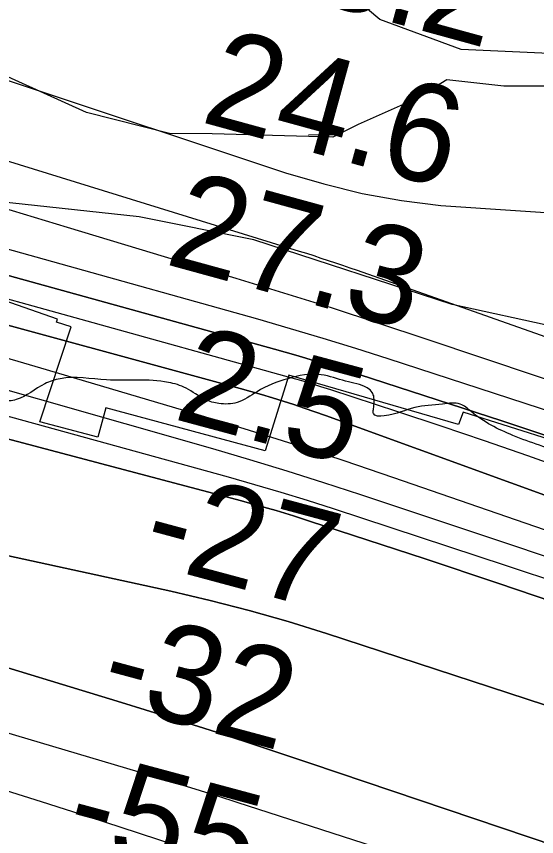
# Model space of a CAD drawing. Extents: x 3329297 to 3367176, y 649250 to 674653.
# Drawn here: x 3335095 to 3335450, y 671176 to 671736 of the extents above; entities that cross this region are included whole.
import ezdxf

# ---------------------------------------------------------------- set-up
doc = ezdxf.new("R2010")
doc.units = 0
for name, color, linetype in [('V-BORW-LINE', 7, 'Continuous'), ('V-RIVR-EDGE', 7, 'Continuous'), ('V-RIVR-RANG', 7, 'Continuous'), ('V-RRAP-RVMT', 7, 'Continuous'), ('V-SITE-VEGE', 7, 'Continuous'), ('V-TOPO-DPTH', 7, 'Continuous'), ('V-TOPO-MAJR', 7, 'Continuous'), ('V-TOPO-MINR', 7, 'Continuous'), ('V-TOPO-WATR', 7, 'Continuous'), ('V-WETL-SWMP', 7, 'Continuous')]:
    doc.layers.add(name, color=color, linetype=linetype)

msp = doc.modelspace()

# ---------------------------------------------------------------- linework, layer by layer
at = {"layer": 'V-BORW-LINE'}
msp.add_lwpolyline([(3335544.13, 671706.51), (3335398.54, 671713), (3335343.11, 671733.58), (3335283.83, 671783.37)], dxfattribs=at)
at = {"layer": 'V-RIVR-EDGE'}
msp.add_spline([(3339166.35, 669632.45), (3339148.52, 669636.37), (3339138.83, 669636.78), (3339122.94, 669641.48), (3339105.12, 669646.95), (3339096.99, 669652.01), (3339093.12, 669656.29), (3339089.26, 669664.44), (3339086.56, 669669.1), (3339078.82, 669674.94), (3339053.64, 669688.18), (3339028.47, 669702.21), (3339020.72, 669706.49), (3339018, 669704.17), (3339012.57, 669704.57), (3339008.7, 669708.07), (3339008.32, 669710.4), (3339007.94, 669713.12), (3339007.56, 669715.06), (3338988.58, 669723.63), (3338974.64, 669732.59), (3338973.09, 669734.53), (3338972.71, 669738.02), (3338974.27, 669740.35), (3338974.28, 669743.84), (3338966.94, 669753.94), (3338965.01, 669758.6), (3338963.85, 669760.54), (3338956.49, 669764.43), (3338944.87, 669769.5), (3338928.21, 669778.08), (3338920.86, 669785.07), (3338906.56, 669803.34), (3338897.28, 669814.22), (3338888, 669824.71), (3338880.26, 669833.26), (3338874.07, 669838.71), (3338867.87, 669840.27), (3338862.06, 669843), (3338858.57, 669843.01), (3338858.58, 669844.95), (3338858.24, 669867.83), (3338860.58, 669870.93), (3338861.75, 669873.25), (3338861.76, 669876.35), (3338860.21, 669879.46), (3338854.02, 669882.58), (3338849.02, 669903.14), (3338843.63, 669917.51), (3338832.81, 669931.11), (3338822.75, 669940.83), (3338804.56, 669955.22), (3338800.68, 669956.78), (3338796.03, 669956.79), (3338788.66, 669955.26), (3338782.44, 669952.17), (3338775.47, 669955.68), (3338770.44, 669960.35), (3338765.41, 669965.01), (3338754.18, 669972.41), (3338742.57, 669981.36), (3338728.24, 669988.76), (3338714.68, 669995), (3338701.13, 670003.56), (3338693.4, 670012.11), (3338687.99, 670020.27), (3338682.59, 670033.47), (3338677.18, 670040.46), (3338665.17, 670046.31), (3338655.1, 670048.66), (3338655.48, 670045.95), (3338653.54, 670045.56), (3338643.46, 670046.36), (3338635.32, 670050.26), (3338633, 670052.98), (3338626.41, 670055.33), (3338615.17, 670057.29), (3338608.97, 670058.08), (3338601.61, 670062.76), (3338592.32, 670069.37), (3338582.25, 670071.72), (3338574.11, 670074.46), (3338568.3, 670078.74), (3338562.5, 670084.57), (3338561.34, 670087.67), (3338554.75, 670088.85), (3338551.26, 670089.25), (3338548.94, 670091.97), (3338544.31, 670098.58), (3338517.19, 670108.73), (3338513.32, 670111.84), (3338511.39, 670115.72), (3338497.82, 670118.86), (3338480, 670125.88), (3338471.48, 670130.17), (3338466.45, 670134.83), (3338451.73, 670140.3), (3338441.26, 670142.65), (3338438.16, 670142.27), (3338431.18, 670145.39), (3338420.34, 670150.07), (3338407.93, 670152.43), (3338393.21, 670156.73), (3338378.49, 670165.69), (3338345.2, 670189.43), (3338316.55, 670206.56), (3338280.93, 670231.47), (3338237.55, 670254.45), (3338210.45, 670270.81), (3338182.57, 670289.88), (3338148.9, 670317.5), (3338126.07, 670336.94), (3338116.01, 670348.22), (3338106.73, 670356.77), (3338093.56, 670363.78), (3338076.9, 670368.87), (3338057.53, 670376.28), (3338042.81, 670383.3), (3338026.54, 670392.65), (3338007.18, 670402.39), (3337994, 670405.52), (3337971.52, 670413.34), (3337948.66, 670420.76), (3337916.51, 670434.03), (3337912.65, 670440.63), (3337911.11, 670448.78), (3337908.8, 670453.82), (3337904.54, 670455.77), (3337890.98, 670459.68), (3337883.62, 670464.74), (3337879.36, 670466.69), (3337872.38, 670467.1), (3337862.68, 670467.12), (3337849.88, 670465.99), (3337839.8, 670463.69), (3337826.22, 670462.56), (3337810.72, 670465.7), (3337802.19, 670469.21), (3337788.25, 670478.16), (3337779.73, 670480.51), (3337774.3, 670481.69), (3337768.89, 670486.74), (3337764.63, 670490.63), (3337755.72, 670494.92), (3337749.13, 670496.88), (3337745.26, 670497.27), (3337740.6, 670495.35), (3337738.66, 670496.13), (3337735.18, 670499.24), (3337729.76, 670503.52), (3337724.73, 670508.18), (3337720.08, 670512.07), (3337706.13, 670514.43), (3337677.86, 670531.18), (3337643.77, 670545.22), (3337600.78, 670567.05), (3337560.1, 670585.37), (3337510.14, 670611.87), (3337463.28, 670636.42), (3337442.36, 670644.22), (3337416.78, 670652.43), (3337405.55, 670657.5), (3337401.68, 670661.39), (3337400.13, 670663.33), (3337395.49, 670665.67), (3337388.89, 670666.07), (3337376.88, 670670.76), (3337362.94, 670677.77), (3337340.87, 670690.62), (3337309.5, 670706.99), (3337291.29, 670714.79), (3337276.18, 670722.97), (3337252.56, 670736.99), (3337220.04, 670756.85), (3337154.99, 670798.5), (3337124.41, 670821.07), (3337111.24, 670827.31), (3337094.19, 670832.78), (3337075.97, 670836.7), (3337050.39, 670842.59), (3337028.69, 670849.62), (3337007.78, 670860.53), (3336991.89, 670867.94), (3336983.37, 670871.06), (3336969.03, 670873.42), (3336939.95, 670875.43), (3336901.97, 670884.45), (3336863.6, 670895.79), (3336821.37, 670910.63), (3336786.5, 670926.23), (3336740.02, 670949.61), (3336682.31, 670976.12), (3336635.44, 670997.18), (3336603.68, 671013.55), (3336585.47, 671022.51), (3336583.15, 671026.4), (3336580.06, 671031.06), (3336576.19, 671034.56), (3336549.46, 671045.09), (3336500.24, 671058.01), (3336451.41, 671070.16), (3336425.44, 671074.49), (3336399.85, 671076.49), (3336361.07, 671078.91), (3336337.43, 671082.85), (3336313.4, 671088.34), (3336290.92, 671094.6), (3336280.46, 671097.34), (3336275.41, 671097.35), (3336257.58, 671097.39), (3336194.82, 671123.92), (3336129.35, 671154.33), (3336078.61, 671179.66), (3336032.91, 671203.04), (3335979.46, 671230.32), (3335943.05, 671245.54), (3335907.79, 671259.2), (3335894.23, 671264.66), (3335887.64, 671265.45), (3335873.31, 671273.63), (3335871.38, 671277.13), (3335862.86, 671281.41), (3335831.09, 671293.51), (3335799.33, 671308.72), (3335763.7, 671327.42), (3335724.58, 671346.9), (3335714.51, 671351.97), (3335703.27, 671355.1), (3335699.01, 671358.21), (3335680.04, 671369.9), (3335645.95, 671385.49), (3335603.71, 671399.17), (3335573.09, 671406.61), (3335518.06, 671419.93), (3335470.4, 671436.73), (3335433.98, 671449.62), (3335405.32, 671465.97), (3335397.96, 671471.03), (3335385.94, 671471.06), (3335366.94, 671468.78), (3335345.98, 671463.02), (3335338.62, 671464.59), (3335338.62, 671467.3), (3335339.03, 671475.83), (3335337.87, 671478.94), (3335334.39, 671482.05), (3335319.67, 671486.74), (3335303, 671491.05), (3335280.12, 671488.39), (3335259.15, 671479.52), (3335245.56, 671472.19), (3335233.15, 671471.44), (3335223.85, 671474.18), (3335210.68, 671481.97), (3335198.67, 671485.88), (3335156.4, 671487.53), (3335124.61, 671488.39), (3335114.13, 671484.92), (3335094.71, 671474.11), (3335085.4, 671473.36), (3335075.32, 671475.71), (3335065.63, 671477.67), (3335064.86, 671478.45), (3335067.59, 671483.1), (3335066.81, 671484.65), (3335063.72, 671489.31), (3335039.71, 671501.39), (3335020.73, 671509.2), (3335003.28, 671511.95), (3334994.76, 671515.46), (3334990.89, 671517.03), (3334963, 671533.38), (3334933.18, 671549.36), (3334916.12, 671551.34), (3334894.42, 671557.6), (3334863.43, 671571.25), (3334847.95, 671581.75), (3334834.78, 671587.99), (3334809.21, 671598.53), (3334767.76, 671617.24), (3334744.9, 671627.77), (3334711.2, 671642.2), (3334691.44, 671649.23), (3334670.12, 671653.16), (3334647.65, 671659.81), (3334620.14, 671672.29), (3334605.42, 671678.53), (3334581, 671683.24), (3334555.81, 671689.12), (3334542.23, 671688.38), (3334534.09, 671688.79), (3334531.39, 671696.55), (3334523.66, 671706.27), (3334505.85, 671714.84), (3334480.26, 671719.17), (3334460.49, 671721.93), (3334457, 671720.39), (3334455.05, 671716.91), (3334456.59, 671713.8), (3334463.19, 671714.56), (3334467.45, 671712.22), (3334467.44, 671710.28), (3334462.78, 671708.35), (3334446.88, 671706.84), (3334429.04, 671707.66), (3334403.46, 671713.93), (3334397.66, 671718.6), (3334391.46, 671722.88), (3334378.67, 671723.69), (3334340.28, 671727.27), (3334305.39, 671730.07), (3334290.26, 671730.11), (3334281.35, 671731.68), (3334271.66, 671734.81), (3334266.23, 671735.6), (3334258.08, 671732.9), (3334246.43, 671726.73), (3334241.39, 671726.35), (3334232.48, 671729.48), (3334218.91, 671729.9), (3334190.6, 671730.74), (3334178.97, 671731.94), (3334163.47, 671737.4), (3334156.1, 671736.65), (3334151.44, 671732.39), (3334148.33, 671732.4), (3334142.53, 671735.91), (3334132.83, 671736.32), (3334110.73, 671737.53), (3334106.86, 671739.48), (3334099.89, 671744.15), (3334081.28, 671748.08), (3334072.75, 671747.71), (3334041.74, 671753.61), (3334018.09, 671757.54), (3334010.35, 671760.28), (3333999.89, 671767.67), (3333992.15, 671771.95), (3333987.1, 671771.19), (3333984.38, 671768.48), (3333980.12, 671768.49), (3333976.64, 671772.77), (3333969.66, 671775.11), (3333958.81, 671778.24), (3333949.91, 671783.31), (3333945.64, 671782.93), (3333941.37, 671782.16), (3333931.3, 671788.01), (3333925.87, 671788.02), (3333915.4, 671788.82), (3333900.29, 671791.57), (3333878.2, 671798.61), (3333856.9, 671811.07), (3333845.68, 671822.73), (3333832.9, 671828.97), (3333818.18, 671834.82), (3333817.41, 671837.15), (3333813.53, 671837.55), (3333800.36, 671841.85), (3333795.71, 671844.96), (3333793.79, 671851.56), (3333792.24, 671854.28), (3333782.95, 671858.18), (3333767.85, 671869.46), (3333755.47, 671879.57), (3333746.17, 671884.64), (3333742.68, 671886.2), (3333733.76, 671885.83), (3333720.97, 671886.64), (3333714.38, 671889.76), (3333707.8, 671895.2), (3333701.62, 671902.59), (3333696.98, 671908.42), (3333690.4, 671913.09), (3333677.23, 671920.49), (3333664.47, 671934.87), (3333650.92, 671945.76), (3333635.04, 671952), (3333625.75, 671959.78), (3333617.63, 671968.72), (3333606.39, 671969.91), (3333600.97, 671974.19), (3333597.87, 671978.08), (3333590.14, 671988.96), (3333572.36, 672009.16), (3333553.4, 672029.38), (3333532.11, 672045.72), (3333511.21, 672062.06), (3333486.44, 672080.35), (3333466.3, 672090.87), (3333451.59, 672102.92), (3333445.79, 672109.53), (3333446.58, 672114.96), (3333429.16, 672126.25), (3333421.43, 672137.9), (3333420.68, 672148.76), (3333415.26, 672151.1), (3333404.71, 672151.61)], degree=3, dxfattribs=at)
at = {"layer": 'V-RRAP-RVMT'}
for p, q in [((3335122.99, 671529.04), (3335008.31, 671568.73)), ((3335122.31, 671526.98), (3335122.99, 671529.04)), ((3335132.32, 671523.73), (3335122.31, 671526.98)), ((3335110.81, 671458.96), (3335132.32, 671523.73)), ((3335280.94, 671490.89), (3335264.68, 671439.19)), ((3335396.88, 671457.13), (3335280.94, 671490.89)), ((3335156.01, 671468.56), (3335150.35, 671448.52)), ((3335264.68, 671439.19), (3335156.01, 671468.56)), ((3335399.92, 671465.52), (3335396.88, 671457.13)), ((3335520.69, 671427.27), (3335399.92, 671465.52)), ((3335150.35, 671448.52), (3335110.81, 671458.96))]:
    msp.add_line(p, q, dxfattribs=at)
at = {"layer": 'V-SITE-VEGE'}
for p, q in [((3335178.56, 671598.82), (3335057.01, 671612.1)), ((3335256.94, 671583.2), (3335178.56, 671598.82)), ((3335392.38, 671539), (3335256.94, 671583.2)), ((3335468.16, 671522.52), (3335392.38, 671539))]:
    msp.add_line(p, q, dxfattribs=at)
at = {"layer": 'V-TOPO-DPTH'}
for points in [[(3334414.81, 671708.42), (3335247.62, 671481.74), (3335254.98, 671479.69), (3335262.32, 671477.57), (3335269.64, 671475.37), (3335276.94, 671473.11), (3335284.21, 671470.77), (3335291.46, 671468.35), (3335298.68, 671465.85), (3335305.88, 671463.29), (3335880.48, 671254.56), (3335895, 671249.28), (3335909.52, 671243.98), (3335924.03, 671238.66), (3335938.54, 671233.32), (3335958.74, 671225.88), (3335963.14, 671224.26), (3335967.55, 671222.63), (3335971.95, 671221.01), (3335976.36, 671219.39), (3336088.25, 671178.28), (3336148.58, 671156.07), (3336208.9, 671133.8)], [(3336208.9, 671133.8), (3336148.58, 671156.07), (3336088.25, 671178.28), (3335976.36, 671219.39), (3335971.95, 671221.01), (3335967.55, 671222.63), (3335963.14, 671224.26), (3335958.74, 671225.88), (3335938.54, 671233.32), (3335924.03, 671238.66), (3335909.52, 671243.98), (3335895, 671249.28), (3335880.48, 671254.56), (3335305.88, 671463.29), (3335298.68, 671465.85), (3335291.46, 671468.35), (3335284.21, 671470.77), (3335276.94, 671473.11), (3335269.64, 671475.37), (3335262.32, 671477.57), (3335254.98, 671479.69), (3335247.62, 671481.74), (3334414.81, 671708.42)], [(3334571.7, 671701.28), (3334636.35, 671683.68), (3334700.98, 671665.97), (3334765.58, 671648.18), (3335271.14, 671508.5), (3335285.64, 671504.39), (3335300.1, 671500.15), (3335314.5, 671495.72), (3335328.86, 671491.16), (3335426.31, 671459.51), (3335489.28, 671438.79), (3335552.15, 671417.76), (3335614.86, 671396.25), (3335677.46, 671374.43), (3335919.24, 671289.15), (3335948.69, 671278.79), (3335978.15, 671268.47), (3336007.64, 671258.22), (3336037.13, 671247.99), (3336091.93, 671229.07), (3336148.79, 671209.27), (3336205.57, 671189.27)], [(3336568.33, 670959.43), (3336013.25, 671169.68), (3335986.6, 671179.73), (3335959.92, 671189.73), (3335933.22, 671199.65), (3335906.49, 671209.52), (3335826.24, 671239.01), (3335759.26, 671263.28), (3335692.15, 671287.15), (3335624.82, 671310.41), (3335557.36, 671333.28), (3335329.99, 671409.19), (3335304.86, 671417.39), (3335279.66, 671425.37), (3335254.36, 671433.01), (3335228.99, 671440.42), (3334753.05, 671576.09), (3334687.65, 671594.63), (3334622.21, 671613.06), (3334556.73, 671631.3)], [(3336568.33, 670959.43), (3336013.25, 671169.68), (3335986.6, 671179.73), (3335959.92, 671189.73), (3335933.22, 671199.65), (3335906.49, 671209.52), (3335826.24, 671239.01), (3335759.26, 671263.28), (3335692.15, 671287.15), (3335624.82, 671310.41), (3335557.36, 671333.28), (3335329.99, 671409.19), (3335304.86, 671417.39), (3335279.66, 671425.37), (3335254.36, 671433.01), (3335228.99, 671440.42), (3334753.05, 671576.09), (3334687.65, 671594.63), (3334622.21, 671613.06), (3334556.73, 671631.3)], [(3334388.23, 671617.01), (3334612.96, 671565.53), (3334723.34, 671539.65), (3334833.53, 671513.02), (3334943.44, 671485.27), (3335053.17, 671456.77), (3335248.59, 671404.94), (3335260.44, 671401.69), (3335272.25, 671398.31), (3335284, 671394.72), (3335295.71, 671391), (3335373.28, 671365.6), (3335423.66, 671348.82), (3335473.92, 671331.71), (3335524, 671314.09), (3335573.97, 671296.13), (3335929.91, 671166.13), (3335941.22, 671161.95), (3335952.51, 671157.69), (3335963.76, 671153.34), (3335974.98, 671148.92), (3336067.07, 671112.17), (3336124.17, 671088.97), (3336181.05, 671065.27)], [(3336181.05, 671065.27), (3336124.17, 671088.97), (3336067.07, 671112.17), (3335974.98, 671148.92), (3335963.76, 671153.34), (3335952.51, 671157.69), (3335941.22, 671161.95), (3335929.91, 671166.13), (3335573.97, 671296.13), (3335524, 671314.09), (3335473.92, 671331.71), (3335423.66, 671348.82), (3335373.28, 671365.6), (3335295.71, 671391), (3335284, 671394.72), (3335272.25, 671398.31), (3335260.44, 671401.69), (3335248.59, 671404.94), (3335053.17, 671456.77), (3334943.44, 671485.27), (3334833.53, 671513.02), (3334723.34, 671539.65), (3334612.96, 671565.53), (3334388.23, 671617.01)], [(3334519.27, 671499.19), (3334616.45, 671474.69), (3334713.81, 671450.95), (3334811.45, 671428.35), (3334909.26, 671406.52), (3335200.32, 671343.34), (3335227.16, 671337.08), (3335253.85, 671330.27), (3335280.33, 671322.65), (3335306.65, 671314.49), (3335592.62, 671220.97), (3335650.83, 671201.08), (3335708.65, 671180.18), (3335765.91, 671157.75), (3335822.78, 671134.31), (3335889.72, 671105.67), (3335912.79, 671095.69), (3335935.79, 671085.57), (3335958.71, 671075.25), (3335981.57, 671064.8), (3336024.87, 671044.77), (3336069.52, 671024.66), (3336114.42, 671005.14), (3336159.71, 670986.52)], [(3334519.27, 671499.19), (3334616.45, 671474.69), (3334713.81, 671450.95), (3334811.45, 671428.35), (3334909.26, 671406.52), (3335200.32, 671343.34), (3335227.16, 671337.08), (3335253.85, 671330.27), (3335280.33, 671322.65), (3335306.65, 671314.49), (3335592.62, 671220.97), (3335650.83, 671201.08), (3335708.65, 671180.18), (3335765.91, 671157.75), (3335822.78, 671134.31), (3335889.72, 671105.67), (3335912.79, 671095.69), (3335935.79, 671085.57), (3335958.71, 671075.25), (3335981.57, 671064.8), (3336024.87, 671044.77), (3336069.52, 671024.66), (3336114.42, 671005.14), (3336159.71, 670986.52)], [(3336780.8, 670656.12), (3335991.84, 670987.78), (3335955.59, 671001.14), (3335919.26, 671014.3), (3335882.83, 671027.15), (3335846.32, 671039.81), (3335835.6, 671043.48), (3335793.67, 671057.79), (3335751.73, 671072.06), (3335709.77, 671086.28), (3335667.79, 671100.46), (3335295.98, 671225.76), (3335263.71, 671236.48), (3335231.39, 671247), (3335198.97, 671257.24), (3335166.49, 671267.3), (3335055.88, 671301), (3334967.96, 671327.48), (3334879.94, 671353.56), (3334791.74, 671379.07), (3334703.43, 671404.18), (3334375.38, 671496.31)], [(3334375.38, 671496.31), (3334703.43, 671404.18), (3334791.74, 671379.07), (3334879.94, 671353.56), (3334967.96, 671327.48), (3335055.88, 671301), (3335166.49, 671267.3), (3335198.97, 671257.24), (3335231.39, 671247), (3335263.71, 671236.48), (3335295.98, 671225.76), (3335667.79, 671100.46), (3335709.77, 671086.28), (3335751.73, 671072.06), (3335793.67, 671057.79), (3335835.6, 671043.48), (3335846.32, 671039.81), (3335882.83, 671027.15), (3335919.26, 671014.3), (3335955.59, 671001.14), (3335991.84, 670987.78), (3336780.8, 670656.12)]]:
    msp.add_lwpolyline(points, dxfattribs=at)
at = {"layer": 'V-TOPO-MAJR'}
for points in [[(3334465.48, 671896.3), (3334643.39, 671838.51), (3334755.96, 671801.81), (3334868.47, 671764.96), (3334980.91, 671727.87), (3335093.3, 671690.62), (3335278.64, 671628.98), (3335304.71, 671621.28), (3335331.03, 671614.78), (3335357.74, 671610.08), (3335384.69, 671606.58), (3336027.26, 671563.57), (3336045.4, 671559.52), (3336063.42, 671555), (3336909.83, 671212.05)], [(3336745.9, 671099.99), (3335993.18, 671327.49), (3335992.53, 671327.69), (3335990.58, 671328.31), (3335986.29, 671329.71), (3335983.51, 671330.63), (3335980.72, 671331.57), (3335977.95, 671332.53), (3335975.18, 671333.49), (3335327.68, 671562.13), (3335322.77, 671563.85), (3335317.85, 671565.55), (3335312.93, 671567.23), (3335308, 671568.9), (3335303.06, 671570.53), (3335298.12, 671572.15), (3335293.16, 671573.72), (3335288.2, 671575.28), (3334446.57, 671835.68)], [(3336703.56, 670649.65), (3335910.18, 670975.35), (3335892.72, 670981.52), (3335875.23, 670987.58), (3335554.94, 671096.99), (3335499.37, 671115.82), (3335443.75, 671134.48), (3335388.03, 671152.86), (3335332.25, 671171.07), (3335245.61, 671199.12), (3335233.1, 671203.12), (3335220.56, 671207.06), (3335208, 671210.91), (3335195.42, 671214.69), (3334355.15, 671464.35)]]:
    msp.add_lwpolyline(points, dxfattribs=at)
at = {"layer": 'V-TOPO-MINR'}
for points in [[(3336405.56, 671176.91), (3336006.54, 671304), (3335997.14, 671307.01), (3335987.76, 671310.06), (3335978.39, 671313.14), (3335969.03, 671316.26), (3335911.48, 671335.54), (3335873.36, 671348.32), (3335835.23, 671361.09), (3335797.11, 671373.87), (3335758.98, 671386.65), (3335374.73, 671515.47), (3335342.39, 671526.15), (3335309.99, 671536.64), (3335277.49, 671546.83), (3335244.93, 671556.82), (3335129.62, 671591.66), (3335039.38, 671618.99), (3334949.17, 671646.41), (3334858.99, 671673.97), (3334768.85, 671701.61), (3334439.84, 671802.75)], [(3335473.42, 671425.18), (3335444.03, 671435.69), (3335414.58, 671446.01), (3335385.02, 671456.03), (3335355.4, 671465.85), (3335309.65, 671480.76), (3335302.84, 671482.93), (3335296, 671485.04), (3335289.14, 671487.06), (3335282.26, 671489.01), (3335134.93, 671529.87), (3335054.36, 671552.14), (3334973.76, 671574.32), (3334893.12, 671596.36), (3334812.45, 671618.3), (3334402.65, 671729.38)], [(3336176.69, 671225.39), (3336021.06, 671277.58), (3336002.13, 671283.95), (3335983.21, 671290.35), (3335964.3, 671296.79), (3335945.39, 671303.26), (3335837.85, 671340.18), (3335765.13, 671364.96), (3335692.33, 671389.49), (3335619.41, 671413.68), (3335546.42, 671437.64), (3335348.84, 671501.94), (3335326.63, 671509.02), (3335304.37, 671515.91), (3335282.02, 671522.51), (3335259.61, 671528.93), (3334559.51, 671724.79)], [(3336205.57, 671189.27), (3336148.79, 671209.27), (3336091.93, 671229.07), (3336037.13, 671247.99), (3336007.64, 671258.22), (3335978.15, 671268.47), (3335948.69, 671278.79), (3335919.24, 671289.15), (3335677.46, 671374.43), (3335614.86, 671396.25), (3335552.15, 671417.76), (3335489.28, 671438.79), (3335426.31, 671459.51), (3335328.86, 671491.16), (3335314.5, 671495.72), (3335300.1, 671500.15), (3335285.64, 671504.39), (3335271.14, 671508.5), (3334765.58, 671648.18), (3334700.98, 671665.97), (3334636.35, 671683.68), (3334571.7, 671701.28)], [(3336645.9, 670952.8), (3336032.85, 671180.51), (3335998.29, 671193.33), (3335963.73, 671206.13), (3335929.15, 671218.91), (3335894.56, 671231.66), (3335882.46, 671236.12), (3335841.77, 671250.96), (3335801.02, 671265.63), (3335760.19, 671280.05), (3335719.29, 671294.3), (3335352.71, 671420.76), (3335318.7, 671432.25), (3335284.6, 671443.43), (3335250.35, 671454.17), (3335216.01, 671464.61), (3335115.47, 671494.46), (3335030.71, 671519.32), (3334945.84, 671543.82), (3334860.81, 671567.75), (3334775.68, 671591.32), (3334427.53, 671686.46)], [(3336568.33, 670959.43), (3336013.25, 671169.68), (3335986.6, 671179.73), (3335959.92, 671189.73), (3335933.22, 671199.65), (3335906.49, 671209.52), (3335826.24, 671239.01), (3335759.26, 671263.28), (3335692.15, 671287.15), (3335624.82, 671310.41), (3335557.36, 671333.28), (3335329.99, 671409.19), (3335304.86, 671417.39), (3335279.66, 671425.37), (3335254.36, 671433.01), (3335228.99, 671440.42), (3334753.05, 671576.09), (3334687.65, 671594.63), (3334622.21, 671613.06), (3334556.73, 671631.3)], [(3336181.05, 671065.27), (3336124.17, 671088.97), (3336067.07, 671112.17), (3335974.98, 671148.92), (3335963.76, 671153.34), (3335952.51, 671157.69), (3335941.22, 671161.95), (3335929.91, 671166.13), (3335573.97, 671296.13), (3335524, 671314.09), (3335473.92, 671331.71), (3335423.66, 671348.82), (3335373.28, 671365.6), (3335295.71, 671391), (3335284, 671394.72), (3335272.25, 671398.31), (3335260.44, 671401.69), (3335248.59, 671404.94), (3335053.17, 671456.77), (3334943.44, 671485.27), (3334833.53, 671513.02), (3334723.34, 671539.65), (3334612.96, 671565.53), (3334388.23, 671617.01)], [(3336275.84, 671049.71), (3335993.93, 671159.11), (3335975.07, 671166.37), (3335956.18, 671173.56), (3335937.25, 671180.64), (3335918.29, 671187.65), (3335735.55, 671254.61), (3335659.4, 671282.07), (3335583.06, 671309), (3335506.45, 671335.13), (3335429.65, 671360.73), (3335311.44, 671399.45), (3335293.57, 671405.16), (3335275.65, 671410.7), (3335257.65, 671415.99), (3335239.59, 671421.1), (3334519.31, 671619.54)], [(3336159.71, 670986.52), (3336114.42, 671005.14), (3336069.52, 671024.66), (3336024.87, 671044.77), (3335981.57, 671064.8), (3335958.71, 671075.25), (3335935.79, 671085.57), (3335912.79, 671095.69), (3335889.72, 671105.67), (3335822.78, 671134.31), (3335765.91, 671157.75), (3335708.65, 671180.18), (3335650.83, 671201.08), (3335592.62, 671220.97), (3335306.65, 671314.49), (3335280.33, 671322.65), (3335253.85, 671330.27), (3335227.16, 671337.08), (3335200.32, 671343.34), (3334909.26, 671406.52), (3334811.45, 671428.35), (3334713.81, 671450.95), (3334616.45, 671474.69), (3334519.27, 671499.19)], [(3336780.8, 670656.12), (3335991.84, 670987.78), (3335955.59, 671001.14), (3335919.26, 671014.3), (3335882.83, 671027.15), (3335846.32, 671039.81), (3335835.6, 671043.48), (3335793.67, 671057.79), (3335751.73, 671072.06), (3335709.77, 671086.28), (3335667.79, 671100.46), (3335295.98, 671225.76), (3335263.71, 671236.48), (3335231.39, 671247), (3335198.97, 671257.24), (3335166.49, 671267.3), (3335055.88, 671301), (3334967.96, 671327.48), (3334879.94, 671353.56), (3334791.74, 671379.07), (3334703.43, 671404.18), (3334375.38, 671496.31)], [(3334358.25, 671422.77), (3335013.2, 671229.77), (3335046.14, 671219.93), (3335079.02, 671209.93), (3335111.83, 671199.69), (3335144.59, 671189.29), (3335177.27, 671178.64), (3335209.9, 671167.83), (3335242.45, 671156.79), (3335274.94, 671145.58), (3335769.82, 670972.84), (3335791.52, 670964.79), (3335813, 670956.21), (3335834.13, 670946.81), (3335855.03, 670936.86), (3335875.03, 670926.88), (3336707.54, 670617.4)]]:
    msp.add_lwpolyline(points, dxfattribs=at)
at = {"layer": 'V-TOPO-WATR'}
msp.add_lwpolyline([(3336208.9, 671133.8), (3336148.58, 671156.07), (3336088.25, 671178.28), (3335976.36, 671219.39), (3335971.95, 671221.01), (3335967.55, 671222.63), (3335963.14, 671224.26), (3335958.74, 671225.88), (3335938.54, 671233.32), (3335924.03, 671238.66), (3335909.52, 671243.98), (3335895, 671249.28), (3335880.48, 671254.56), (3335305.88, 671463.29), (3335298.68, 671465.85), (3335291.46, 671468.35), (3335284.21, 671470.77), (3335276.94, 671473.11), (3335269.64, 671475.37), (3335262.32, 671477.57), (3335254.98, 671479.69), (3335247.62, 671481.74), (3334414.81, 671708.42)], dxfattribs=at)
at = {"layer": 'V-WETL-SWMP'}
for p, q in [((3335142.6, 671670.1), (3335073.57, 671701.32)), ((3335388.81, 671692.29), (3335367.16, 671679.29)), ((3335427.78, 671687.96), (3335388.81, 671692.29)), ((3335462.42, 671687.96), (3335427.78, 671687.96)), ((3335367.16, 671679.29), (3335328.2, 671661.96)), ((3335199.43, 671655.84), (3335142.6, 671670.1)), ((3335328.2, 671661.96), (3335310.88, 671653.3)), ((3335228.59, 671655.58), (3335199.43, 671655.84)), ((3335310.88, 671653.3), (3335228.59, 671655.58)), ((3335294.43, 671654.93), (3335314.21, 671654.96))]:
    msp.add_line(p, q, dxfattribs=at)

# ---------------------------------------------------------------- texts
at = {"layer": 'V-RIVR-RANG'}
for s, rotation, p in [('23.2', 344.6783, (3335247.54, 671759.97)), ('24.6', 344.6783, (3335219.57, 671663.94)), ('27.3', 344.6783, (3335195.16, 671566.95)), ('2.5', 344.9591, (3335201.07, 671461.21)), ('-27', 344.9591, (3335178.44, 671363.74)), ('-32', 344.9591, (3335149.46, 671267.98)), ('-55', 344.9591, (3335125.82, 671170.79))]:
    msp.add_text(s, height=67, rotation=rotation, dxfattribs=at).set_placement(p)

doc.saveas('drawing.dxf')
